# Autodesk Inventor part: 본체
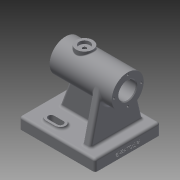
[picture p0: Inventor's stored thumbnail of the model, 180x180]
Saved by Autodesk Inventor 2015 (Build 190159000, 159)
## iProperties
Created: 2022-06
Part Number: 본체
Material: 일반
Document SubType Name: Modeling
Designer: 10415
Density: 1 g/cm^3
Appearance: 기본값
Author: 10415
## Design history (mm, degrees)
sketch "스케치1"
  geometry: L1 (50, -43)-(-50, -43); L2 (-50, -43)-(-50, 43); L3 (-50, 43)-(50, 43); L4 (50, 43)-(50, -43); L5 (50, -43)-(-50, 43); L6 (-50, -43)-(50, 43); 1 further point
  constraints: 12 end point, 2 midpoint, 2 parallel, 1 horizontal, 1 perpendicular
  dimensions: "d0" = 100 distance of L2.end L3.end; "d1" = 86 distance of L1.end L2.end
extrude "돌출1" new body sketch "스케치1" distance "d2" = 15; taper "d3" = 0 deg
sketch "스케치5"
  geometry: L1 (-50, -43)-(50, -43) reference; L2 (50, -43)-(50, 43) reference; L3 (-50, 43)-(-50, -43) reference; L4 (-35, 5)-(35, 5); L5 (35, 5)-(35, -5); L6 (35, -5)-(-35, -5); L7 (-35, -5)-(-35, 5); 1 further point
  constraints: 8 end point, 2 parallel, 1 horizontal, 1 perpendicular
  dimensions: "d18" = 15 distance between parallel lines of L2 L5; "d20" = 15 distance between parallel lines of L3 L7; "d21" = 10 distance of L4.end L5.end; "d22" = 38 distance between parallel lines of L1 L6
extrude "돌출3" join sketch "스케치5" distance "d23" = 57; taper "d24" = 0 deg
feature "면 기울기2" dims angle "d27" = 20 deg
sketch "스케치6"
  geometry: L1 (32, 93)-(-50, 93); L2 (-50, 93)-(-50, 72); L3 (-50, 72)-(32, 72); L4 (32, 72)-(32, 93); L5 (-50, 0)-(-50, 15) reference; L6 (-50, 15)-(-35, 15) reference; L7 (-35, 15)-(-35, 72) reference; L8 (-35, 72)-(14.254, 72) reference; L9 (14.254, 72)-(35, 15) reference; L10 (35, 15)-(50, 15) reference; L11 (50, 15)-(50, 0) reference; L12 (50, 0)-(-50, 0) reference; 1 further point
  constraints: 8 end point, 2 collinear, 2 parallel, 1 horizontal, 1 perpendicular
  dimensions: "d25" = 21 distance of L1.end L2.end; "d26" = 82 distance of L1.start L1.end
revolve "회전2" sketch "스케치6" stored, may be unused: angle "d28" = 90 deg
sketch "스케치7"
  geometry: L1 (15, -38)-(0, -38) reference; L2 (0, -38)-(0, 0) reference; L3 (0, 0)-(-36.604, 0) reference; L4 (-36.604, 10)-(0, 10) reference; L5 (0, 10)-(0, 48) reference; L6 (0, 48)-(15, 48) reference; L7 (15, 48)-(15, -38) reference; L8 (0, 0)-(0, 10) reference; L9 (0, -30)-(-61.814, -15.441); L10 (-61.814, 25.441)-(0, 40); L11 (0, 10)-(-36.604, 10) reference; A1 r 21 centre (-57, 5) between (-36.604, 0) and (-36.604, 10) reference; A2 r 21 centre (-57, 5) between (-36.604, 10) and (-36.604, 0) reference; A3 r 21 centre (-57, 5) between (-36.604, 0) and (-36.604, 10) reference; 1 further point
  constraints: 4 end point, 2 point on circle, 2 point on line, 2 tangent
  dimensions: "d29" = 8 distance from line of L1 L9.start; "d30" = 8 distance from line of L6 L10.end
  node "절단 모서리 투영3"
sketch "스케치8"
  geometry: C1 r 21 at (0, 0) reference; C2 r 14.5 at (0, 0); 1 further point
  constraints: 1 centre point, 1 coincident
  dimensions: "d33" = 29 diameter of C2
extrude "돌출5" cut sketch "스케치8" distance "d34" = 62; taper "d35" = 0 deg
sketch "스케치9"
  geometry: C1 r 14.5 at (0, 0) reference; C2 r 11.5 at (0, 0); 1 further point
  constraints: 1 centre point, 1 coincident
  dimensions: "d36" = 23 diameter of C2
extrude "돌출6" cut sketch "스케치9" stored distance "d37" = 62; taper "d38" = 0 deg
extrude "돌출7" join sketch "스케치7" distance "d41" = 10; taper "d42" = 0 deg
node "작업 평면3"
sketch "스케치10"
  geometry: L1 (-32, 21)-(-32, -21) reference; C1 r 11 at (-7, 0); 1 further point
  constraints: 1 centre point, 1 horizontal alignment
  dimensions: "d44" = 22 diameter of C1; "d45" = 25 distance from line of L1 C1.centre
extrude "돌출8" join sketch "스케치10" stored distance "d46" = 10; taper "d47" = 0 deg
sketch "스케치11"
  geometry: C1 r 11 at (0, 0) reference; 1 further point
hole "구멍1" sketch "스케치11" at (0, 0) diameter "d48" = 4.917; stored, may be unused: countersink angle "d52" = 90 deg, drill point angle "d54" = 118 deg; dims "d49" = 12, "d50" = 14, "d51" = 4, "d53" = 21
sketch "스케치12"
  geometry: C1 r 11.5 at (0, 0) reference; 2 further points
  constraints: 1 horizontal alignment
  dimensions: "d55" = 18 distance of C1.centre point (-18, 0)
hole "구멍2" sketch "스케치12" at (-18, 0) diameter "d56" = 2.459; stored, may be unused: countersink angle "d60" = 90 deg, drill point angle "d62" = 118 deg; dims "d57" = 8, "d58" = 14, "d59" = 4, "d61" = 10
node "작업 평면4"
sketch "스케치13"
  geometry: L1 (-50, -43)-(50, -43) reference; L2 (-50, 43)-(-50, -43) reference; L3 (-24, -27)-(-12, -27); L4 (-24, -34)-(-12, -34); L5 (-12, -20)-(-24, -20); A1 r 7 centre (-24, -27) between (-24, -20) and (-24, -34); A2 r 7 centre (-12, -27) between (-12, -34) and (-12, -20); 2 further points
  constraints: 8 end point, 4 point on circle, 4 tangent, 2 centre point, 1 horizontal, 1 midpoint, 1 parallel
  dimensions: "d66" = 26 distance from line of L2 L3.start; "d67" = 12 distance of L3.start L3.end; "d68" = 16 distance from line of L1 L3.start; "d69" = 14 distance between parallel lines of L4 L5
extrude "돌출9" join sketch "스케치13" distance "d70" = 3; taper "d71" = 0 deg
sketch "스케치14"
  geometry: L1 (-12, -27)-(-24, -27); L2 (-12, -23)-(-24, -23); L3 (-24, -31)-(-12, -31); A1 r 7 centre (-12, -27) between (-12, -34) and (-12, -20) reference; A2 r 7 centre (-24, -27) between (-24, -20) and (-24, -34) reference; A3 r 4 centre (-12, -27) between (-12, -31) and (-12, -23); A4 r 4 centre (-24, -27) between (-24, -23) and (-24, -31); 2 further points
  constraints: 8 end point, 4 point on circle, 4 tangent, 2 centre point, 1 horizontal, 1 midpoint, 1 parallel
  dimensions: "d72" = 8 diameter of A4
extrude "돌출10" cut sketch "스케치14" stored distance "d73" = 3; taper "d74" = 0 deg
fillet "모깎기1" dims "d75" = 3
fillet "모깎기2" dims "d76" = 3
fillet "모깎기3" dims "d77" = 1
chamfer "모따기1" distance "d78" = 1; stored, may be unused: second distance "d79" = 2, angle "d80" = 45 deg
sketch "스케치15"
  geometry: L1 (0, 80)-(0, 0) reference; 3 further points
  constraints: 1 horizontal alignment, 1 midpoint, 1 other
  dimensions: "d81" = 6 distance from line of L1 point (-6, 40)
feature "엠보싱1" sketch "스케치15" dims "d0" = 100, "d1" = 86, "d25" = 21, "d26" = 82, "d82" = 0.5, "d83" = 0
fillet "모깎기4" dims "d84" = 3
node "솔리드1"
pattern_circular "원형 패턴1" dims angle "d64" = 360 deg
mirror "대칭1"
node "절단 모서리 투영2"
other parameters: "d43" = 96
